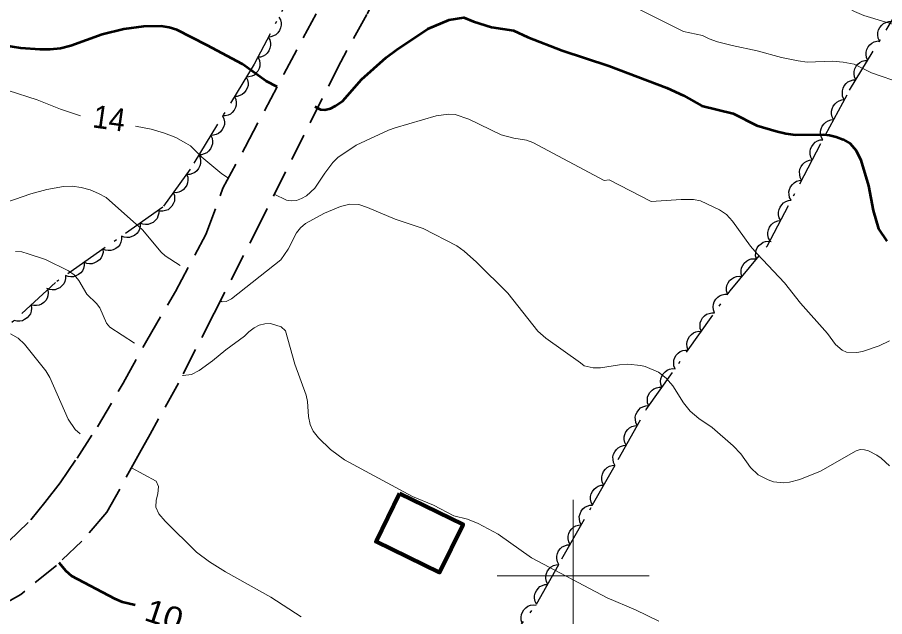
# Model space of a CAD drawing. Extents: x 356765 to 358572, y 5103174 to 5104650.
# Drawn here: x 357663.4 to 357720.5, y 5103497.3 to 5103536.7 of the extents above; entities that cross this region are included whole.
import ezdxf
from ezdxf.enums import TextEntityAlignment as Align

# ---------------------------------------------------------------- set-up
doc = ezdxf.new("R2010")
doc.units = 0
doc.header["$LTSCALE"] = 0.6
doc.linetypes.add('DOT_DASHED', pattern=[7.7, 5, -1.2, 0.3, -1.2])
doc.linetypes.add('MEDIUM_DASHED', pattern=[4.5, 3, -1.5])
for name, color, linetype, lineweight in [('1', 7, 'Continuous', 53), ('2', 7, 'Continuous', 13), ('21', 7, 'Continuous', 53), ('37', 7, 'Continuous', 13), ('44', 7, 'Continuous', 25), ('61', 7, 'Continuous', 13)]:
    doc.layers.add(name, color=color, linetype=linetype, lineweight=lineweight)

msp = doc.modelspace()

# ---------------------------------------------------------------- linework, layer by layer
at = {"layer": '1'}
for points in [[(357682.99, 5103530.88), (357683.35, 5103530.68), (357683.65, 5103530.65), (357684.01, 5103530.75), (357684.35, 5103530.92), (357684.84, 5103531.24), (357686.07, 5103532.65), (357687.68, 5103534.1), (357688.36, 5103534.6), (357690.42, 5103535.99), (357691.83, 5103536.57), (357692.8, 5103536.72), (357693.44, 5103536.46), (357694.62, 5103536.09), (357696.07, 5103535.87), (357697.01, 5103535.44), (357699.28, 5103534.57), (357702.35, 5103533.55), (357706.17, 5103532.1), (357707.26, 5103531.59), (357708.47, 5103530.92), (357710.53, 5103530.41), (357712.1, 5103529.63), (357713.37, 5103529.24), (357714, 5103529.09), (357714.61, 5103529.01), (357716.5, 5103529.03), (357716.87, 5103528.99), (357717.31, 5103528.88), (357717.77, 5103528.7), (357718.23, 5103528.43), (357718.62, 5103527.98), (357718.93, 5103527.34), (357719.45, 5103525.66), (357719.75, 5103524.03), (357720.09, 5103522.83), (357720.65, 5103522.01)], [(357680.5, 5103532.16), (357679.79, 5103532.55), (357678.22, 5103533.65), (357675.87, 5103534.9), (357673.89, 5103535.91), (357673.4, 5103536.08), (357672.87, 5103536.16), (357671.71, 5103536.13), (357670.41, 5103535.97), (357668.99, 5103535.61), (357666.92, 5103534.86), (357666.24, 5103534.7), (357665.57, 5103534.63), (357664.89, 5103534.63), (357663.62, 5103534.72), (357661.97, 5103534.97)], [(357671.15, 5103498.05), (357670.33, 5103498.26), (357669.81, 5103498.47), (357666.98, 5103499.97), (357666.61, 5103500.29), (357666.16, 5103500.85)]]:
    msp.add_lwpolyline(points, dxfattribs=at)
at = {"layer": '2'}
for points in [[(357721.67, 5103536.09), (357719.14, 5103536.87), (357718.52, 5103537.13), (357717.66, 5103537.58), (357716.07, 5103538.15), (357715.48, 5103538.26), (357714.34, 5103538.57), (357712.65, 5103539.2), (357711.16, 5103539.45), (357710.26, 5103539.66), (357709.41, 5103540.03), (357708.74, 5103540.23), (357708.17, 5103540.63), (357708.1, 5103540.93), (357704.73, 5103541.65), (357703.38, 5103541.68)], [(357721.67, 5103532.38), (357719.64, 5103533.09), (357718.49, 5103533.66), (357717.77, 5103533.8), (357717.08, 5103533.86), (357715.41, 5103533.8), (357714.8, 5103533.87), (357713.72, 5103534.09), (357712.12, 5103534.53), (357710.46, 5103534.88), (357709.51, 5103535.13), (357708.95, 5103535.32), (357708.52, 5103535.54), (357707.25, 5103535.8), (357704.06, 5103537.42), (357694.67, 5103538.86), (357694.05, 5103538.86), (357693.47, 5103538.79), (357692.93, 5103538.65), (357692.43, 5103538.5), (357690.22, 5103537.51)], [(357667.56, 5103530.26), (357666.24, 5103530.69), (357664.7, 5103531.32), (357662.8, 5103531.92)], [(357720.83, 5103515.45), (357720.15, 5103515.12), (357719.04, 5103514.75), (357718.68, 5103514.68), (357717.99, 5103514.7), (357717.7, 5103514.83), (357717.27, 5103515.22), (357716.74, 5103515.94), (357714.97, 5103517.93), (357713.92, 5103519.28), (357712.11, 5103521.17), (357711.68, 5103521.69), (357710.49, 5103523.33), (357710.1, 5103523.76), (357709.63, 5103524.07), (357708.37, 5103524.66), (357707.92, 5103524.76), (357707.11, 5103524.76), (357705.13, 5103524.63), (357702.36, 5103526.05), (357702.03, 5103526.01), (357697.33, 5103528.5), (357696.93, 5103528.66), (357696.1, 5103528.79), (357695.26, 5103529), (357693.13, 5103530.04), (357692.22, 5103530.34), (357691.79, 5103530.37), (357690.97, 5103530.26), (357688.28, 5103529.46), (357687.83, 5103529.32), (357685.7, 5103528.34), (357684.51, 5103527.51), (357684.17, 5103527.18), (357683.65, 5103526.49), (357682.99, 5103525.49), (357682.44, 5103525), (357682.11, 5103524.82), (357681.77, 5103524.69), (357681.43, 5103524.66), (357681.13, 5103524.71), (357680.32, 5103525.1)], [(357677.3, 5103526.15), (357676.87, 5103526.44), (357675.55, 5103527.54), (357674.8, 5103528.28), (357674.5, 5103528.47), (357673.83, 5103528.83), (357673.08, 5103529.12), (357672.21, 5103529.38), (357671.19, 5103529.58)], [(357674.11, 5103520.42), (357673.13, 5103521.05), (357672.86, 5103521.29), (357671.64, 5103522.76), (357669.25, 5103524.88), (357668.75, 5103525.16), (357668.19, 5103525.4), (357667.61, 5103525.55), (357667.02, 5103525.63), (357666.43, 5103525.62), (357665.35, 5103525.41), (357664.28, 5103525.12), (357660.47, 5103523.82)], [(357720.83, 5103507.23), (357720.27, 5103507.73), (357719.98, 5103507.94), (357719.44, 5103508.22), (357719.17, 5103508.28), (357718.89, 5103508.3), (357718.63, 5103508.22), (357716.29, 5103506.88), (357714.93, 5103506.32), (357714.23, 5103506.15), (357713.87, 5103506.12), (357713.19, 5103506.18), (357712.84, 5103506.3), (357712.18, 5103506.63), (357711.68, 5103507.13), (357711.03, 5103508.01), (357710.52, 5103508.54), (357709.15, 5103509.76), (357708.27, 5103510.34), (357707.71, 5103510.82), (357707.26, 5103511.37), (357706.55, 5103512.5), (357706.12, 5103513), (357705.61, 5103513.4), (357704.74, 5103513.76), (357704.46, 5103513.83), (357703.6, 5103513.91), (357703.05, 5103513.88), (357701.79, 5103513.67), (357701.32, 5103513.68), (357700.71, 5103513.8), (357700.49, 5103514.01), (357698.2, 5103515.62), (357697.68, 5103516.09), (357695.7, 5103518.58), (357693.63, 5103520.63), (357692.82, 5103521.36), (357692.33, 5103521.71), (357690.12, 5103522.84), (357688.27, 5103523.46), (357686.46, 5103524.23), (357685.88, 5103524.42), (357685.29, 5103524.45), (357684.68, 5103524.3), (357683.62, 5103523.86), (357682.38, 5103523.18), (357682.05, 5103522.88), (357681.79, 5103522.55), (357681.23, 5103521.49), (357680.74, 5103520.79), (357677.5, 5103518.22), (357677.16, 5103518.05), (357676.89, 5103518.01), (357676.78, 5103518.09)], [(357671.11, 5103515.3), (357669.49, 5103516.36), (357669.27, 5103516.62), (357668.84, 5103517.62), (357668.62, 5103517.9), (357667.97, 5103518.53), (357667.44, 5103519.43), (357667.14, 5103519.8), (357666.77, 5103520.07), (357665.25, 5103520.8), (357664.11, 5103521.19), (357663.7, 5103521.3), (357663.27, 5103521.34)], [(357705.64, 5103497.01), (357704.11, 5103497.76), (357702.24, 5103498.55), (357697.25, 5103501.18), (357695.05, 5103502.73), (357693.75, 5103503.44), (357693.03, 5103503.72), (357692.15, 5103503.94), (357690.81, 5103504.63), (357689.41, 5103505.21), (357684.94, 5103507.62), (357684.01, 5103508.3), (357683.23, 5103509.08), (357682.88, 5103509.5), (357682.68, 5103509.95), (357682.58, 5103510.47), (357682.51, 5103511.46), (357682.41, 5103511.88), (357681.66, 5103513.91), (357681.05, 5103516.11), (357680.77, 5103516.38), (357680.06, 5103516.59), (357679.69, 5103516.58), (357679.32, 5103516.48), (357678.99, 5103516.3), (357678.65, 5103516.04), (357678.36, 5103515.76), (357677.12, 5103514.86), (357676.26, 5103514.13), (357675.38, 5103513.51), (357674.86, 5103513.23), (357674.32, 5103513.17), (357674.27, 5103513.18)], [(357667.53, 5103509.34), (357667.21, 5103509.63), (357666.75, 5103510.3), (357665.53, 5103513.04), (357665.28, 5103513.48), (357663.87, 5103515.23), (357663.45, 5103515.63), (357662.95, 5103515.92)], [(357682.09, 5103497.3), (357680.08, 5103498.58), (357677.1, 5103500.26), (357676.06, 5103500.92), (357675.19, 5103501.55), (357673.13, 5103503.59), (357672.71, 5103504.08), (357672.52, 5103504.51), (357672.53, 5103504.96), (357672.64, 5103505.38), (357672.7, 5103505.86), (357672.54, 5103506.21), (357670.91, 5103507.09)]]:
    msp.add_lwpolyline(points, dxfattribs=at)
at = {"layer": '21', "linetype": 'MEDIUM_DASHED', "lineweight": 35}
for points in [[(357662.81, 5103502.25), (357664.29, 5103503.67), (357665.22, 5103504.81), (357666.23, 5103506.1), (357667.33, 5103507.73), (357668.68, 5103509.8), (357670.36, 5103512.66), (357671.92, 5103515.48), (357673.81, 5103518.7), (357675.81, 5103522.46), (357676.94, 5103525.49), (357678.4, 5103528.2), (357680.95, 5103533.01), (357684.35, 5103539.37), (357685.94, 5103542.38), (357686.52, 5103543.73), (357688.49, 5103547.59), (357691.63, 5103554), (357694.24, 5103559.54), (357697.1, 5103565.88), (357700.48, 5103573.51), (357706.53, 5103587.93), (357706.78, 5103589.58), (357707.92, 5103596.9)], [(357705.04, 5103574.9), (357703.69, 5103572.38), (357701.47, 5103568.26), (357699.8, 5103565.11), (357698.13, 5103561.68), (357696.16, 5103557.51), (357694.48, 5103553.59), (357692.61, 5103549.49), (357690.71, 5103545.4), (357688.55, 5103540.94), (357686.41, 5103536.93), (357684.69, 5103533.82), (357679.51, 5103523.48), (357676.37, 5103517.28), (357674.01, 5103512.67), (357672.14, 5103509.32), (357671.45, 5103508.06), (357669.3, 5103504.19), (357667.65, 5103502.28), (357665.98, 5103500.68), (357663.63, 5103498.77), (357661.36, 5103497.5)]]:
    msp.add_lwpolyline(points, dxfattribs=at)
at = {"layer": '37', "lineweight": 90}
msp.add_lwpolyline([(357688.56, 5103505.41), (357687.02, 5103502.24), (357691.2, 5103500.21), (357692.75, 5103503.37)], close=True, dxfattribs=at)
at = {"layer": '44', "linetype": 'DOT_DASHED'}
for points in [[(357704.76, 5103584.87), (357696.06, 5103565.8), (357686.48, 5103547.94), (357678.99, 5103533.66), (357674.78, 5103526.75), (357672.97, 5103524.24), (357665.91, 5103519.29), (357662.79, 5103516.42)], [(357694.92, 5103494.6), (357697.59, 5103498.12), (357699.26, 5103501.1), (357701.28, 5103504.67), (357702.96, 5103507.65), (357704.8, 5103510.93), (357710.33, 5103518.75), (357712.78, 5103521.69), (357716.6, 5103529.01), (357718.2, 5103531.95), (357721.68, 5103537.67)]]:
    msp.add_lwpolyline(points, dxfattribs=at)
at = {"layer": '44'}
for points in [[(357680.62, 5103536.76), (357680.72, 5103536.58), (357680.76, 5103536.38), (357680.77, 5103536.22), (357680.73, 5103536.04), (357680.66, 5103535.87), (357680.54, 5103535.72), (357680.43, 5103535.6), (357680.27, 5103535.52), (357680.1, 5103535.46), (357679.92, 5103535.43)], [(357720.17, 5103535.19), (357720.08, 5103535.38), (357720.06, 5103535.58), (357720.06, 5103535.75), (357720.11, 5103535.91), (357720.19, 5103536.08), (357720.31, 5103536.22), (357720.43, 5103536.34), (357720.59, 5103536.41), (357720.77, 5103536.46), (357720.95, 5103536.47)], [(357679.92, 5103535.43), (357680.02, 5103535.25), (357680.06, 5103535.05), (357680.07, 5103534.89), (357680.03, 5103534.72), (357679.96, 5103534.54), (357679.84, 5103534.39), (357679.73, 5103534.27), (357679.58, 5103534.19), (357679.4, 5103534.13), (357679.22, 5103534.11)], [(357719.39, 5103533.91), (357719.3, 5103534.1), (357719.28, 5103534.3), (357719.28, 5103534.46), (357719.33, 5103534.63), (357719.41, 5103534.8), (357719.53, 5103534.94), (357719.65, 5103535.05), (357719.81, 5103535.13), (357719.99, 5103535.18), (357720.17, 5103535.19)], [(357679.25, 5103534.09), (357679.34, 5103533.9), (357679.37, 5103533.7), (357679.37, 5103533.53), (357679.32, 5103533.37), (357679.23, 5103533.2), (357679.11, 5103533.06), (357678.99, 5103532.94), (357678.83, 5103532.87), (357678.65, 5103532.82), (357678.47, 5103532.81)], [(357718.61, 5103532.63), (357718.52, 5103532.82), (357718.5, 5103533.02), (357718.5, 5103533.18), (357718.55, 5103533.35), (357718.63, 5103533.52), (357718.75, 5103533.66), (357718.87, 5103533.77), (357719.03, 5103533.85), (357719.21, 5103533.9), (357719.39, 5103533.91)], [(357678.47, 5103532.81), (357678.56, 5103532.62), (357678.59, 5103532.42), (357678.59, 5103532.25), (357678.54, 5103532.08), (357678.45, 5103531.92), (357678.33, 5103531.77), (357678.21, 5103531.66), (357678.05, 5103531.59), (357677.87, 5103531.54), (357677.69, 5103531.53)], [(357717.83, 5103531.34), (357717.74, 5103531.53), (357717.72, 5103531.74), (357717.72, 5103531.9), (357717.77, 5103532.07), (357717.85, 5103532.24), (357717.97, 5103532.38), (357718.09, 5103532.49), (357718.25, 5103532.57), (357718.43, 5103532.62), (357718.61, 5103532.63)], [(357677.69, 5103531.53), (357677.78, 5103531.34), (357677.81, 5103531.14), (357677.81, 5103530.97), (357677.76, 5103530.8), (357677.67, 5103530.64), (357677.55, 5103530.49), (357677.43, 5103530.38), (357677.27, 5103530.31), (357677.09, 5103530.26), (357676.91, 5103530.25)], [(357717.14, 5103530.01), (357717.05, 5103530.2), (357717.01, 5103530.4), (357717, 5103530.56), (357717.05, 5103530.73), (357717.12, 5103530.9), (357717.24, 5103531.05), (357717.35, 5103531.17), (357717.51, 5103531.25), (357717.68, 5103531.31), (357717.86, 5103531.33)], [(357676.91, 5103530.25), (357677, 5103530.06), (357677.03, 5103529.86), (357677.03, 5103529.69), (357676.98, 5103529.52), (357676.89, 5103529.36), (357676.77, 5103529.21), (357676.65, 5103529.1), (357676.49, 5103529.03), (357676.31, 5103528.98), (357676.13, 5103528.97)], [(357716.43, 5103528.69), (357716.33, 5103528.88), (357716.29, 5103529.08), (357716.29, 5103529.24), (357716.33, 5103529.41), (357716.4, 5103529.58), (357716.52, 5103529.73), (357716.63, 5103529.85), (357716.79, 5103529.93), (357716.97, 5103529.99), (357717.14, 5103530.01)], [(357676.13, 5103528.97), (357676.22, 5103528.78), (357676.24, 5103528.58), (357676.24, 5103528.41), (357676.19, 5103528.24), (357676.11, 5103528.08), (357675.99, 5103527.93), (357675.87, 5103527.82), (357675.71, 5103527.75), (357675.53, 5103527.69), (357675.35, 5103527.69)], [(357715.74, 5103527.36), (357715.64, 5103527.54), (357715.6, 5103527.74), (357715.59, 5103527.91), (357715.63, 5103528.08), (357715.7, 5103528.25), (357715.81, 5103528.4), (357715.93, 5103528.52), (357716.08, 5103528.61), (357716.25, 5103528.67), (357716.43, 5103528.69)], [(357675.35, 5103527.69), (357675.44, 5103527.5), (357675.46, 5103527.29), (357675.46, 5103527.13), (357675.41, 5103526.96), (357675.33, 5103526.8), (357675.21, 5103526.65), (357675.09, 5103526.54), (357674.93, 5103526.46), (357674.75, 5103526.41), (357674.57, 5103526.4)], [(357715.04, 5103526.03), (357714.95, 5103526.21), (357714.91, 5103526.41), (357714.89, 5103526.58), (357714.93, 5103526.75), (357715, 5103526.92), (357715.12, 5103527.07), (357715.23, 5103527.19), (357715.39, 5103527.28), (357715.56, 5103527.34), (357715.74, 5103527.36)], [(357674.54, 5103526.42), (357674.62, 5103526.23), (357674.63, 5103526.02), (357674.61, 5103525.86), (357674.55, 5103525.69), (357674.46, 5103525.54), (357674.32, 5103525.4), (357674.19, 5103525.3), (357674.03, 5103525.24), (357673.85, 5103525.2), (357673.67, 5103525.21)], [(357714.35, 5103524.7), (357714.25, 5103524.88), (357714.21, 5103525.08), (357714.2, 5103525.25), (357714.24, 5103525.42), (357714.31, 5103525.59), (357714.43, 5103525.74), (357714.54, 5103525.86), (357714.69, 5103525.95), (357714.87, 5103526.01), (357715.04, 5103526.03)], [(357673.67, 5103525.21), (357673.74, 5103525.01), (357673.75, 5103524.81), (357673.74, 5103524.64), (357673.67, 5103524.48), (357673.58, 5103524.32), (357673.44, 5103524.18), (357673.32, 5103524.08), (357673.15, 5103524.02), (357672.97, 5103523.98), (357672.79, 5103523.99)], [(357713.66, 5103523.37), (357713.56, 5103523.55), (357713.52, 5103523.75), (357713.51, 5103523.92), (357713.55, 5103524.09), (357713.62, 5103524.26), (357713.73, 5103524.41), (357713.84, 5103524.53), (357714, 5103524.62), (357714.17, 5103524.68), (357714.35, 5103524.7)], [(357672.72, 5103524.06), (357672.72, 5103523.85), (357672.66, 5103523.66), (357672.6, 5103523.51), (357672.48, 5103523.37), (357672.34, 5103523.25), (357672.17, 5103523.17), (357672.02, 5103523.12), (357671.84, 5103523.11), (357671.66, 5103523.14), (357671.49, 5103523.2)], [(357671.49, 5103523.2), (357671.49, 5103522.99), (357671.44, 5103522.8), (357671.37, 5103522.65), (357671.26, 5103522.51), (357671.11, 5103522.39), (357670.94, 5103522.31), (357670.79, 5103522.26), (357670.61, 5103522.25), (357670.43, 5103522.28), (357670.26, 5103522.34)], [(357712.96, 5103522.04), (357712.86, 5103522.22), (357712.82, 5103522.42), (357712.81, 5103522.59), (357712.85, 5103522.76), (357712.92, 5103522.93), (357713.04, 5103523.08), (357713.15, 5103523.2), (357713.3, 5103523.29), (357713.48, 5103523.35), (357713.66, 5103523.37)], [(357670.26, 5103522.34), (357670.26, 5103522.13), (357670.21, 5103521.94), (357670.14, 5103521.78), (357670.03, 5103521.65), (357669.89, 5103521.53), (357669.71, 5103521.45), (357669.56, 5103521.39), (357669.38, 5103521.39), (357669.2, 5103521.41), (357669.03, 5103521.48)], [(357712.07, 5103520.84), (357712.01, 5103521.04), (357712.02, 5103521.25), (357712.04, 5103521.41), (357712.12, 5103521.57), (357712.22, 5103521.72), (357712.37, 5103521.84), (357712.5, 5103521.94), (357712.67, 5103521.99), (357712.85, 5103522.01), (357713.03, 5103521.99)], [(357669.03, 5103521.48), (357669.04, 5103521.27), (357668.98, 5103521.07), (357668.91, 5103520.92), (357668.8, 5103520.79), (357668.66, 5103520.67), (357668.49, 5103520.59), (357668.33, 5103520.53), (357668.16, 5103520.53), (357667.97, 5103520.55), (357667.8, 5103520.62)], [(357711.11, 5103519.69), (357711.05, 5103519.89), (357711.06, 5103520.09), (357711.08, 5103520.26), (357711.16, 5103520.42), (357711.26, 5103520.57), (357711.41, 5103520.69), (357711.54, 5103520.78), (357711.71, 5103520.84), (357711.89, 5103520.86), (357712.07, 5103520.84)], [(357667.8, 5103520.62), (357667.81, 5103520.41), (357667.75, 5103520.21), (357667.69, 5103520.06), (357667.57, 5103519.93), (357667.43, 5103519.81), (357667.26, 5103519.73), (357667.1, 5103519.67), (357666.93, 5103519.67), (357666.74, 5103519.69), (357666.58, 5103519.76)], [(357666.58, 5103519.76), (357666.58, 5103519.55), (357666.52, 5103519.35), (357666.46, 5103519.2), (357666.34, 5103519.07), (357666.2, 5103518.95), (357666.03, 5103518.87), (357665.88, 5103518.81), (357665.7, 5103518.81), (357665.52, 5103518.83), (357665.35, 5103518.9)], [(357710.15, 5103518.54), (357710.09, 5103518.74), (357710.1, 5103518.94), (357710.12, 5103519.1), (357710.2, 5103519.26), (357710.3, 5103519.42), (357710.45, 5103519.54), (357710.58, 5103519.63), (357710.75, 5103519.68), (357710.93, 5103519.71), (357711.11, 5103519.69)], [(357665.4, 5103518.82), (357665.44, 5103518.62), (357665.41, 5103518.42), (357665.36, 5103518.26), (357665.27, 5103518.11), (357665.14, 5103517.97), (357664.98, 5103517.87), (357664.83, 5103517.8), (357664.66, 5103517.77), (357664.48, 5103517.77), (357664.3, 5103517.81)], [(357709.3, 5103517.3), (357709.23, 5103517.49), (357709.22, 5103517.7), (357709.23, 5103517.86), (357709.29, 5103518.03), (357709.38, 5103518.19), (357709.52, 5103518.32), (357709.64, 5103518.42), (357709.81, 5103518.49), (357709.99, 5103518.53), (357710.17, 5103518.52)], [(357664.3, 5103517.81), (357664.33, 5103517.6), (357664.3, 5103517.4), (357664.26, 5103517.24), (357664.16, 5103517.09), (357664.04, 5103516.96), (357663.88, 5103516.85), (357663.73, 5103516.78), (357663.56, 5103516.75), (357663.37, 5103516.75), (357663.2, 5103516.79)], [(357708.44, 5103516.07), (357708.36, 5103516.27), (357708.35, 5103516.47), (357708.36, 5103516.64), (357708.42, 5103516.8), (357708.52, 5103516.96), (357708.65, 5103517.1), (357708.78, 5103517.2), (357708.94, 5103517.26), (357709.12, 5103517.3), (357709.3, 5103517.3)], [(357707.57, 5103514.85), (357707.5, 5103515.04), (357707.48, 5103515.25), (357707.5, 5103515.41), (357707.56, 5103515.58), (357707.65, 5103515.74), (357707.79, 5103515.87), (357707.91, 5103515.98), (357708.08, 5103516.04), (357708.26, 5103516.08), (357708.44, 5103516.07)], [(357706.71, 5103513.62), (357706.63, 5103513.82), (357706.62, 5103514.02), (357706.63, 5103514.19), (357706.69, 5103514.35), (357706.78, 5103514.51), (357706.92, 5103514.65), (357707.05, 5103514.75), (357707.21, 5103514.81), (357707.39, 5103514.85), (357707.57, 5103514.85)], [(357705.84, 5103512.4), (357705.77, 5103512.6), (357705.75, 5103512.8), (357705.76, 5103512.96), (357705.83, 5103513.13), (357705.92, 5103513.29), (357706.05, 5103513.42), (357706.18, 5103513.53), (357706.34, 5103513.59), (357706.53, 5103513.63), (357706.71, 5103513.62)], [(357704.97, 5103511.18), (357704.9, 5103511.37), (357704.89, 5103511.57), (357704.9, 5103511.74), (357704.96, 5103511.9), (357705.05, 5103512.06), (357705.19, 5103512.2), (357705.31, 5103512.3), (357705.48, 5103512.37), (357705.66, 5103512.4), (357705.84, 5103512.4)], [(357704.21, 5103509.88), (357704.12, 5103510.07), (357704.09, 5103510.27), (357704.08, 5103510.44), (357704.12, 5103510.61), (357704.2, 5103510.77), (357704.32, 5103510.92), (357704.43, 5103511.04), (357704.59, 5103511.12), (357704.77, 5103511.18), (357704.95, 5103511.19)], [(357703.48, 5103508.58), (357703.39, 5103508.76), (357703.35, 5103508.96), (357703.35, 5103509.13), (357703.39, 5103509.3), (357703.47, 5103509.47), (357703.59, 5103509.62), (357703.7, 5103509.73), (357703.86, 5103509.81), (357704.03, 5103509.87), (357704.21, 5103509.88)], [(357702.75, 5103507.27), (357702.65, 5103507.45), (357702.62, 5103507.65), (357702.61, 5103507.82), (357702.66, 5103507.99), (357702.73, 5103508.16), (357702.85, 5103508.31), (357702.97, 5103508.42), (357703.12, 5103508.5), (357703.3, 5103508.56), (357703.48, 5103508.58)], [(357702.01, 5103505.96), (357701.91, 5103506.15), (357701.88, 5103506.35), (357701.88, 5103506.51), (357701.92, 5103506.68), (357702, 5103506.85), (357702.12, 5103507), (357702.23, 5103507.12), (357702.39, 5103507.2), (357702.57, 5103507.25), (357702.74, 5103507.27)], [(357701.27, 5103504.65), (357701.18, 5103504.84), (357701.14, 5103505.04), (357701.14, 5103505.21), (357701.18, 5103505.38), (357701.26, 5103505.55), (357701.38, 5103505.69), (357701.5, 5103505.81), (357701.65, 5103505.89), (357701.83, 5103505.95), (357702.01, 5103505.96)], [(357700.53, 5103503.35), (357700.44, 5103503.54), (357700.41, 5103503.74), (357700.4, 5103503.9), (357700.45, 5103504.07), (357700.52, 5103504.24), (357700.64, 5103504.39), (357700.76, 5103504.5), (357700.92, 5103504.58), (357701.09, 5103504.64), (357701.27, 5103504.65)], [(357699.79, 5103502.04), (357699.7, 5103502.23), (357699.67, 5103502.43), (357699.66, 5103502.6), (357699.71, 5103502.77), (357699.78, 5103502.93), (357699.9, 5103503.08), (357700.02, 5103503.2), (357700.18, 5103503.28), (357700.35, 5103503.33), (357700.53, 5103503.35)], [(357699.06, 5103500.74), (357698.96, 5103500.92), (357698.93, 5103501.13), (357698.92, 5103501.29), (357698.97, 5103501.46), (357699.04, 5103501.63), (357699.17, 5103501.78), (357699.28, 5103501.89), (357699.44, 5103501.97), (357699.61, 5103502.03), (357699.79, 5103502.04)], [(357698.32, 5103499.43), (357698.23, 5103499.62), (357698.2, 5103499.82), (357698.19, 5103499.98), (357698.23, 5103500.15), (357698.31, 5103500.32), (357698.43, 5103500.47), (357698.54, 5103500.58), (357698.7, 5103500.66), (357698.88, 5103500.72), (357699.06, 5103500.74)], [(357697.59, 5103498.12), (357697.5, 5103498.31), (357697.46, 5103498.51), (357697.46, 5103498.67), (357697.5, 5103498.84), (357697.58, 5103499.01), (357697.7, 5103499.16), (357697.81, 5103499.28), (357697.97, 5103499.36), (357698.14, 5103499.41), (357698.32, 5103499.43)], [(357696.64, 5103496.87), (357696.58, 5103497.07), (357696.57, 5103497.27), (357696.59, 5103497.44), (357696.65, 5103497.6), (357696.75, 5103497.76), (357696.89, 5103497.89), (357697.02, 5103497.99), (357697.19, 5103498.05), (357697.37, 5103498.08), (357697.55, 5103498.07)]]:
    msp.add_lwpolyline(points, dxfattribs=at)
at = {"layer": '61'}
for p, q in [((357700, 5103495), (357700, 5103505)), ((357695, 5103500), (357705, 5103500))]:
    msp.add_line(p, q, dxfattribs=at)

# ---------------------------------------------------------------- texts
at = {"layer": '1', "width": 1.1}
msp.add_text('10', height=1.5, rotation=341.787, dxfattribs=at).set_placement((357672.8356, 5103496.7098), align=Align.CENTER)
at = {"layer": '2', "width": 0.95}
msp.add_text('14', height=1.5, rotation=352, dxfattribs=at).set_placement((357669.3456, 5103529.3602), align=Align.CENTER)

doc.saveas('drawing.dxf')
